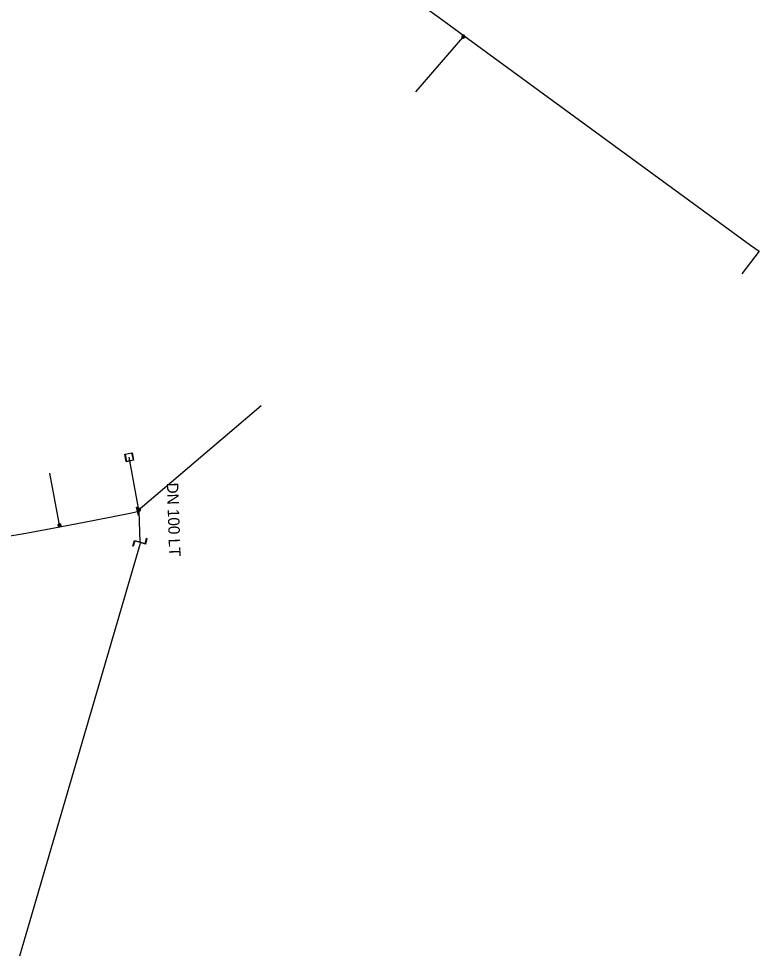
# Model space of a CAD drawing. Extents: x -832382 to -831581, y -1074670 to -1074251.
# Drawn here: x -831710.5 to -831580.8, y -1074667.1 to -1074502.9 of the extents above; entities that cross this region are included whole.
import ezdxf

# ---------------------------------------------------------------- set-up
doc = ezdxf.new("R2010")
doc.units = 0
for name, color, linetype in [('Přípojka vodovodu', 7, 'Continuous'), ('Přípojkový uzávěr', 7, 'Continuous'), ('Roz-řad', 7, 'Continuous'), ('Roz-řad-popis základní', 7, 'Continuous'), ('Změna materiálu vodovodu', 7, 'Continuous'), ('Řad-šoupě', 7, 'Continuous'), ('Šachta vodovodní', 7, 'Continuous')]:
    doc.layers.add(name, color=color, linetype=linetype)

msp = doc.modelspace()

# ---------------------------------------------------------------- linework, layer by layer
at = {"layer": 'Přípojka vodovodu'}
for points in [[(-831632.51, -1074505.89), (-831632.77, -1074506.19), (-831640.99, -1074515.72)], [(-831689.45, -1074588.91), (-831689.23, -1074588.69), (-831668.04, -1074570.68)], [(-831689.47, -1074589.15), (-831689.45, -1074588.91), (-831689.52, -1074588.66), (-831691.16, -1074579.71)], [(-831703.31, -1074591.9), (-831703.38, -1074591.62), (-831703.46, -1074591.27), (-831705.06, -1074582.5)]]:
    msp.add_lwpolyline(points, dxfattribs=at)
at = {"layer": 'Přípojkový uzávěr'}
for points in [[(-831632.64, -1074505.79), (-831632.57, -1074505.79), (-831632.51, -1074505.82), (-831632.45, -1074505.85), (-831632.42, -1074505.91), (-831632.39, -1074505.97), (-831632.39, -1074506.04), (-831632.39, -1074506.1), (-831632.42, -1074506.16), (-831632.45, -1074506.22), (-831632.51, -1074506.25), (-831632.57, -1074506.29), (-831632.64, -1074506.29), (-831632.7, -1074506.29), (-831632.76, -1074506.25), (-831632.82, -1074506.22), (-831632.85, -1074506.16), (-831632.89, -1074506.1), (-831632.89, -1074506.04), (-831632.89, -1074505.97), (-831632.85, -1074505.91), (-831632.82, -1074505.85), (-831632.76, -1074505.82), (-831632.7, -1074505.79), (-831632.64, -1074505.79)], [(-831632.64, -1074505.81), (-831632.69, -1074505.81), (-831632.75, -1074505.84), (-831632.8, -1074505.87), (-831632.83, -1074505.92), (-831632.86, -1074505.98), (-831632.86, -1074506.04), (-831632.86, -1074506.1), (-831632.83, -1074506.15), (-831632.8, -1074506.2), (-831632.75, -1074506.23), (-831632.7, -1074506.26), (-831632.64, -1074506.26), (-831632.58, -1074506.26), (-831632.52, -1074506.23), (-831632.47, -1074506.2), (-831632.44, -1074506.15), (-831632.41, -1074506.1), (-831632.41, -1074506.04), (-831632.41, -1074505.98), (-831632.44, -1074505.92), (-831632.47, -1074505.87), (-831632.53, -1074505.84), (-831632.58, -1074505.81), (-831632.64, -1074505.81)], [(-831632.64, -1074505.83), (-831632.58, -1074505.83), (-831632.53, -1074505.85), (-831632.48, -1074505.88), (-831632.46, -1074505.93), (-831632.43, -1074505.98), (-831632.43, -1074506.04), (-831632.43, -1074506.09), (-831632.46, -1074506.14), (-831632.48, -1074506.19), (-831632.53, -1074506.22), (-831632.58, -1074506.25), (-831632.64, -1074506.25), (-831632.69, -1074506.25), (-831632.74, -1074506.22), (-831632.79, -1074506.19), (-831632.82, -1074506.14), (-831632.85, -1074506.09), (-831632.85, -1074506.04), (-831632.85, -1074505.98), (-831632.82, -1074505.93), (-831632.79, -1074505.88), (-831632.74, -1074505.85), (-831632.69, -1074505.83), (-831632.64, -1074505.83)], [(-831632.64, -1074505.85), (-831632.72, -1074505.85), (-831632.77, -1074505.9), (-831632.82, -1074505.96), (-831632.82, -1074506.04), (-831632.82, -1074506.11), (-831632.77, -1074506.17), (-831632.71, -1074506.22), (-831632.64, -1074506.22), (-831632.56, -1074506.22), (-831632.5, -1074506.17), (-831632.45, -1074506.11), (-831632.45, -1074506.04), (-831632.45, -1074505.96), (-831632.5, -1074505.9), (-831632.56, -1074505.85), (-831632.64, -1074505.85)], [(-831632.64, -1074505.87), (-831632.57, -1074505.87), (-831632.52, -1074505.92), (-831632.47, -1074505.97), (-831632.47, -1074506.04), (-831632.47, -1074506.1), (-831632.52, -1074506.15), (-831632.57, -1074506.2), (-831632.64, -1074506.2), (-831632.71, -1074506.2), (-831632.75, -1074506.15), (-831632.8, -1074506.1), (-831632.8, -1074506.04), (-831632.8, -1074505.97), (-831632.75, -1074505.92), (-831632.71, -1074505.87), (-831632.64, -1074505.87)], [(-831632.64, -1074505.89), (-831632.7, -1074505.89), (-831632.74, -1074505.93), (-831632.78, -1074505.98), (-831632.78, -1074506.04), (-831632.78, -1074506.1), (-831632.74, -1074506.14), (-831632.7, -1074506.18), (-831632.64, -1074506.18), (-831632.58, -1074506.18), (-831632.54, -1074506.14), (-831632.49, -1074506.1), (-831632.49, -1074506.04), (-831632.49, -1074505.98), (-831632.54, -1074505.93), (-831632.58, -1074505.89), (-831632.64, -1074505.89)], [(-831632.64, -1074505.91), (-831632.58, -1074505.91), (-831632.55, -1074505.95), (-831632.51, -1074505.98), (-831632.51, -1074506.04), (-831632.51, -1074506.09), (-831632.55, -1074506.12), (-831632.59, -1074506.16), (-831632.64, -1074506.16), (-831632.69, -1074506.16), (-831632.73, -1074506.12), (-831632.76, -1074506.09), (-831632.76, -1074506.04), (-831632.76, -1074505.98), (-831632.73, -1074505.95), (-831632.69, -1074505.91), (-831632.64, -1074505.91)], [(-831632.64, -1074505.93), (-831632.68, -1074505.93), (-831632.71, -1074505.96), (-831632.74, -1074505.99), (-831632.74, -1074506.04), (-831632.74, -1074506.08), (-831632.71, -1074506.11), (-831632.68, -1074506.14), (-831632.64, -1074506.14), (-831632.6, -1074506.14), (-831632.57, -1074506.11), (-831632.54, -1074506.08), (-831632.54, -1074506.04), (-831632.54, -1074505.99), (-831632.57, -1074505.96), (-831632.6, -1074505.93), (-831632.64, -1074505.93)], [(-831632.64, -1074505.95), (-831632.6, -1074505.95), (-831632.58, -1074505.98), (-831632.55, -1074506), (-831632.55, -1074506.04), (-831632.55, -1074506.07), (-831632.58, -1074506.1), (-831632.6, -1074506.12), (-831632.64, -1074506.12), (-831632.67, -1074506.12), (-831632.7, -1074506.1), (-831632.72, -1074506.07), (-831632.72, -1074506.04), (-831632.72, -1074506), (-831632.7, -1074505.98), (-831632.67, -1074505.95), (-831632.64, -1074505.95)], [(-831632.64, -1074505.97), (-831632.66, -1074505.97), (-831632.68, -1074505.99), (-831632.7, -1074506.01), (-831632.7, -1074506.04), (-831632.7, -1074506.06), (-831632.68, -1074506.08), (-831632.66, -1074506.1), (-831632.64, -1074506.1), (-831632.61, -1074506.1), (-831632.59, -1074506.08), (-831632.57, -1074506.06), (-831632.57, -1074506.04), (-831632.57, -1074506.01), (-831632.59, -1074505.99), (-831632.61, -1074505.97), (-831632.64, -1074505.97)], [(-831632.64, -1074506), (-831632.62, -1074506), (-831632.61, -1074506.01), (-831632.6, -1074506.02), (-831632.6, -1074506.04), (-831632.6, -1074506.05), (-831632.61, -1074506.06), (-831632.62, -1074506.08), (-831632.64, -1074506.08), (-831632.65, -1074506.08), (-831632.66, -1074506.06), (-831632.68, -1074506.05), (-831632.68, -1074506.04), (-831632.68, -1074506.02), (-831632.66, -1074506.01), (-831632.65, -1074506), (-831632.64, -1074506)], [(-831632.64, -1074506.01), (-831632.65, -1074506.01), (-831632.65, -1074506.02), (-831632.66, -1074506.03), (-831632.66, -1074506.04), (-831632.66, -1074506.05), (-831632.65, -1074506.05), (-831632.65, -1074506.06), (-831632.64, -1074506.06), (-831632.63, -1074506.06), (-831632.62, -1074506.05), (-831632.61, -1074506.05), (-831632.61, -1074506.04), (-831632.61, -1074506.03), (-831632.62, -1074506.02), (-831632.63, -1074506.01), (-831632.64, -1074506.01)], [(-831689.45, -1074588.66), (-831689.39, -1074588.66), (-831689.33, -1074588.69), (-831689.27, -1074588.72), (-831689.23, -1074588.78), (-831689.2, -1074588.84), (-831689.2, -1074588.91), (-831689.2, -1074588.98), (-831689.23, -1074589.03), (-831689.27, -1074589.09), (-831689.33, -1074589.13), (-831689.39, -1074589.16), (-831689.45, -1074589.16), (-831689.51, -1074589.16), (-831689.57, -1074589.13), (-831689.63, -1074589.09), (-831689.67, -1074589.03), (-831689.7, -1074588.98), (-831689.7, -1074588.91), (-831689.7, -1074588.84), (-831689.67, -1074588.78), (-831689.63, -1074588.72), (-831689.57, -1074588.69), (-831689.51, -1074588.66), (-831689.45, -1074588.66)], [(-831689.45, -1074588.68), (-831689.51, -1074588.68), (-831689.56, -1074588.71), (-831689.62, -1074588.74), (-831689.65, -1074588.8), (-831689.68, -1074588.85), (-831689.68, -1074588.91), (-831689.68, -1074588.97), (-831689.65, -1074589.02), (-831689.62, -1074589.08), (-831689.56, -1074589.11), (-831689.51, -1074589.14), (-831689.45, -1074589.14), (-831689.39, -1074589.14), (-831689.34, -1074589.11), (-831689.28, -1074589.08), (-831689.25, -1074589.02), (-831689.22, -1074588.97), (-831689.22, -1074588.91), (-831689.22, -1074588.85), (-831689.25, -1074588.8), (-831689.28, -1074588.74), (-831689.34, -1074588.71), (-831689.39, -1074588.68), (-831689.45, -1074588.68)], [(-831689.45, -1074588.7), (-831689.4, -1074588.7), (-831689.35, -1074588.73), (-831689.3, -1074588.75), (-831689.27, -1074588.8), (-831689.24, -1074588.86), (-831689.24, -1074588.91), (-831689.24, -1074588.96), (-831689.27, -1074589.01), (-831689.3, -1074589.06), (-831689.35, -1074589.09), (-831689.4, -1074589.12), (-831689.45, -1074589.12), (-831689.5, -1074589.12), (-831689.55, -1074589.09), (-831689.6, -1074589.06), (-831689.63, -1074589.01), (-831689.66, -1074588.96), (-831689.66, -1074588.91), (-831689.66, -1074588.86), (-831689.63, -1074588.8), (-831689.6, -1074588.75), (-831689.55, -1074588.73), (-831689.5, -1074588.7), (-831689.45, -1074588.7)], [(-831689.45, -1074588.72), (-831689.53, -1074588.72), (-831689.58, -1074588.78), (-831689.64, -1074588.83), (-831689.64, -1074588.91), (-831689.64, -1074588.99), (-831689.58, -1074589.04), (-831689.53, -1074589.1), (-831689.45, -1074589.1), (-831689.37, -1074589.1), (-831689.32, -1074589.04), (-831689.26, -1074588.99), (-831689.26, -1074588.91), (-831689.26, -1074588.83), (-831689.32, -1074588.78), (-831689.37, -1074588.72), (-831689.45, -1074588.72)], [(-831689.45, -1074588.75), (-831689.38, -1074588.75), (-831689.33, -1074588.79), (-831689.29, -1074588.84), (-831689.29, -1074588.91), (-831689.29, -1074588.98), (-831689.33, -1074589.03), (-831689.38, -1074589.07), (-831689.45, -1074589.07), (-831689.52, -1074589.07), (-831689.57, -1074589.03), (-831689.61, -1074588.98), (-831689.61, -1074588.91), (-831689.61, -1074588.84), (-831689.57, -1074588.79), (-831689.52, -1074588.75), (-831689.45, -1074588.75)], [(-831689.45, -1074588.77), (-831689.51, -1074588.77), (-831689.55, -1074588.81), (-831689.59, -1074588.85), (-831689.59, -1074588.91), (-831689.59, -1074588.97), (-831689.55, -1074589.01), (-831689.51, -1074589.05), (-831689.45, -1074589.05), (-831689.39, -1074589.05), (-831689.35, -1074589.01), (-831689.31, -1074588.97), (-831689.31, -1074588.91), (-831689.31, -1074588.85), (-831689.35, -1074588.81), (-831689.39, -1074588.77), (-831689.45, -1074588.77)], [(-831689.45, -1074588.78), (-831689.4, -1074588.78), (-831689.36, -1074588.82), (-831689.33, -1074588.86), (-831689.33, -1074588.91), (-831689.33, -1074588.96), (-831689.36, -1074589), (-831689.4, -1074589.03), (-831689.45, -1074589.03), (-831689.5, -1074589.03), (-831689.54, -1074589), (-831689.58, -1074588.96), (-831689.58, -1074588.91), (-831689.58, -1074588.86), (-831689.54, -1074588.82), (-831689.5, -1074588.78), (-831689.45, -1074588.78)], [(-831689.45, -1074588.81), (-831689.49, -1074588.81), (-831689.52, -1074588.84), (-831689.55, -1074588.87), (-831689.55, -1074588.91), (-831689.55, -1074588.95), (-831689.52, -1074588.98), (-831689.49, -1074589.01), (-831689.45, -1074589.01), (-831689.41, -1074589.01), (-831689.38, -1074588.98), (-831689.35, -1074588.95), (-831689.35, -1074588.91), (-831689.35, -1074588.87), (-831689.38, -1074588.84), (-831689.41, -1074588.81), (-831689.45, -1074588.81)], [(-831689.45, -1074588.83), (-831689.42, -1074588.83), (-831689.39, -1074588.85), (-831689.37, -1074588.87), (-831689.37, -1074588.91), (-831689.37, -1074588.94), (-831689.39, -1074588.97), (-831689.42, -1074588.99), (-831689.45, -1074588.99), (-831689.49, -1074588.99), (-831689.51, -1074588.97), (-831689.53, -1074588.94), (-831689.53, -1074588.91), (-831689.53, -1074588.87), (-831689.51, -1074588.85), (-831689.49, -1074588.83), (-831689.45, -1074588.83)], [(-831689.45, -1074588.85), (-831689.48, -1074588.85), (-831689.49, -1074588.87), (-831689.51, -1074588.88), (-831689.51, -1074588.91), (-831689.51, -1074588.94), (-831689.49, -1074588.95), (-831689.48, -1074588.97), (-831689.45, -1074588.97), (-831689.42, -1074588.97), (-831689.41, -1074588.95), (-831689.39, -1074588.94), (-831689.39, -1074588.91), (-831689.39, -1074588.88), (-831689.41, -1074588.87), (-831689.42, -1074588.85), (-831689.45, -1074588.85)], [(-831689.45, -1074588.87), (-831689.43, -1074588.87), (-831689.42, -1074588.88), (-831689.41, -1074588.89), (-831689.41, -1074588.91), (-831689.41, -1074588.93), (-831689.42, -1074588.94), (-831689.43, -1074588.95), (-831689.45, -1074588.95), (-831689.47, -1074588.95), (-831689.48, -1074588.94), (-831689.49, -1074588.93), (-831689.49, -1074588.91), (-831689.49, -1074588.89), (-831689.48, -1074588.88), (-831689.47, -1074588.87), (-831689.45, -1074588.87)], [(-831689.45, -1074588.89), (-831689.46, -1074588.89), (-831689.47, -1074588.89), (-831689.47, -1074588.9), (-831689.47, -1074588.91), (-831689.47, -1074588.92), (-831689.47, -1074588.93), (-831689.46, -1074588.93), (-831689.45, -1074588.93), (-831689.44, -1074588.93), (-831689.43, -1074588.93), (-831689.43, -1074588.92), (-831689.43, -1074588.91), (-831689.43, -1074588.9), (-831689.43, -1074588.89), (-831689.44, -1074588.89), (-831689.45, -1074588.89)], [(-831703.38, -1074591.37), (-831703.32, -1074591.37), (-831703.26, -1074591.4), (-831703.2, -1074591.43), (-831703.16, -1074591.49), (-831703.13, -1074591.55), (-831703.13, -1074591.62), (-831703.13, -1074591.69), (-831703.16, -1074591.74), (-831703.2, -1074591.8), (-831703.26, -1074591.84), (-831703.32, -1074591.87), (-831703.38, -1074591.87), (-831703.44, -1074591.87), (-831703.5, -1074591.84), (-831703.56, -1074591.8), (-831703.6, -1074591.74), (-831703.63, -1074591.69), (-831703.63, -1074591.62), (-831703.63, -1074591.55), (-831703.6, -1074591.49), (-831703.56, -1074591.43), (-831703.5, -1074591.4), (-831703.44, -1074591.37), (-831703.38, -1074591.37)], [(-831703.38, -1074591.39), (-831703.44, -1074591.39), (-831703.49, -1074591.42), (-831703.55, -1074591.45), (-831703.58, -1074591.51), (-831703.61, -1074591.56), (-831703.61, -1074591.62), (-831703.61, -1074591.68), (-831703.58, -1074591.73), (-831703.55, -1074591.79), (-831703.49, -1074591.82), (-831703.44, -1074591.85), (-831703.38, -1074591.85), (-831703.32, -1074591.85), (-831703.27, -1074591.82), (-831703.21, -1074591.79), (-831703.18, -1074591.73), (-831703.15, -1074591.68), (-831703.15, -1074591.62), (-831703.15, -1074591.56), (-831703.18, -1074591.51), (-831703.21, -1074591.45), (-831703.27, -1074591.42), (-831703.32, -1074591.39), (-831703.38, -1074591.39)], [(-831703.38, -1074591.41), (-831703.33, -1074591.41), (-831703.28, -1074591.44), (-831703.23, -1074591.46), (-831703.2, -1074591.51), (-831703.17, -1074591.57), (-831703.17, -1074591.62), (-831703.17, -1074591.67), (-831703.2, -1074591.72), (-831703.23, -1074591.77), (-831703.28, -1074591.8), (-831703.33, -1074591.83), (-831703.38, -1074591.83), (-831703.43, -1074591.83), (-831703.48, -1074591.8), (-831703.53, -1074591.77), (-831703.56, -1074591.72), (-831703.59, -1074591.67), (-831703.59, -1074591.62), (-831703.59, -1074591.57), (-831703.56, -1074591.51), (-831703.53, -1074591.46), (-831703.48, -1074591.44), (-831703.43, -1074591.41), (-831703.38, -1074591.41)], [(-831703.38, -1074591.43), (-831703.46, -1074591.43), (-831703.51, -1074591.49), (-831703.57, -1074591.54), (-831703.57, -1074591.62), (-831703.57, -1074591.7), (-831703.51, -1074591.75), (-831703.46, -1074591.81), (-831703.38, -1074591.81), (-831703.3, -1074591.81), (-831703.25, -1074591.75), (-831703.19, -1074591.7), (-831703.19, -1074591.62), (-831703.19, -1074591.54), (-831703.25, -1074591.49), (-831703.3, -1074591.43), (-831703.38, -1074591.43)], [(-831703.38, -1074591.46), (-831703.31, -1074591.46), (-831703.26, -1074591.5), (-831703.22, -1074591.55), (-831703.22, -1074591.62), (-831703.22, -1074591.69), (-831703.26, -1074591.74), (-831703.31, -1074591.78), (-831703.38, -1074591.78), (-831703.45, -1074591.78), (-831703.5, -1074591.74), (-831703.54, -1074591.69), (-831703.54, -1074591.62), (-831703.54, -1074591.55), (-831703.5, -1074591.5), (-831703.45, -1074591.46), (-831703.38, -1074591.46)], [(-831703.38, -1074591.48), (-831703.44, -1074591.48), (-831703.48, -1074591.52), (-831703.52, -1074591.56), (-831703.52, -1074591.62), (-831703.52, -1074591.68), (-831703.48, -1074591.72), (-831703.44, -1074591.76), (-831703.38, -1074591.76), (-831703.32, -1074591.76), (-831703.28, -1074591.72), (-831703.24, -1074591.68), (-831703.24, -1074591.62), (-831703.24, -1074591.56), (-831703.28, -1074591.52), (-831703.32, -1074591.48), (-831703.38, -1074591.48)], [(-831703.38, -1074591.5), (-831703.33, -1074591.5), (-831703.29, -1074591.53), (-831703.26, -1074591.57), (-831703.26, -1074591.62), (-831703.26, -1074591.67), (-831703.29, -1074591.71), (-831703.33, -1074591.75), (-831703.38, -1074591.75), (-831703.43, -1074591.75), (-831703.47, -1074591.71), (-831703.51, -1074591.67), (-831703.51, -1074591.62), (-831703.51, -1074591.57), (-831703.47, -1074591.53), (-831703.43, -1074591.5), (-831703.38, -1074591.5)], [(-831703.38, -1074591.52), (-831703.42, -1074591.52), (-831703.45, -1074591.55), (-831703.48, -1074591.58), (-831703.48, -1074591.62), (-831703.48, -1074591.66), (-831703.45, -1074591.69), (-831703.42, -1074591.72), (-831703.38, -1074591.72), (-831703.34, -1074591.72), (-831703.31, -1074591.69), (-831703.28, -1074591.66), (-831703.28, -1074591.62), (-831703.28, -1074591.58), (-831703.31, -1074591.55), (-831703.34, -1074591.52), (-831703.38, -1074591.52)], [(-831703.38, -1074591.54), (-831703.35, -1074591.54), (-831703.32, -1074591.56), (-831703.3, -1074591.58), (-831703.3, -1074591.62), (-831703.3, -1074591.65), (-831703.32, -1074591.68), (-831703.35, -1074591.7), (-831703.38, -1074591.7), (-831703.42, -1074591.7), (-831703.44, -1074591.68), (-831703.46, -1074591.65), (-831703.46, -1074591.62), (-831703.46, -1074591.58), (-831703.44, -1074591.56), (-831703.42, -1074591.54), (-831703.38, -1074591.54)], [(-831703.38, -1074591.56), (-831703.41, -1074591.56), (-831703.42, -1074591.58), (-831703.44, -1074591.59), (-831703.44, -1074591.62), (-831703.44, -1074591.65), (-831703.42, -1074591.66), (-831703.41, -1074591.68), (-831703.38, -1074591.68), (-831703.35, -1074591.68), (-831703.34, -1074591.66), (-831703.32, -1074591.65), (-831703.32, -1074591.62), (-831703.32, -1074591.59), (-831703.34, -1074591.58), (-831703.35, -1074591.56), (-831703.38, -1074591.56)], [(-831703.38, -1074591.58), (-831703.36, -1074591.58), (-831703.35, -1074591.59), (-831703.34, -1074591.6), (-831703.34, -1074591.62), (-831703.34, -1074591.64), (-831703.35, -1074591.65), (-831703.36, -1074591.66), (-831703.38, -1074591.66), (-831703.4, -1074591.66), (-831703.41, -1074591.65), (-831703.42, -1074591.64), (-831703.42, -1074591.62), (-831703.42, -1074591.6), (-831703.41, -1074591.59), (-831703.4, -1074591.58), (-831703.38, -1074591.58)], [(-831703.38, -1074591.6), (-831703.39, -1074591.6), (-831703.4, -1074591.6), (-831703.4, -1074591.61), (-831703.4, -1074591.62), (-831703.4, -1074591.63), (-831703.4, -1074591.64), (-831703.39, -1074591.64), (-831703.38, -1074591.64), (-831703.37, -1074591.64), (-831703.36, -1074591.64), (-831703.36, -1074591.63), (-831703.36, -1074591.62), (-831703.36, -1074591.61), (-831703.36, -1074591.6), (-831703.37, -1074591.6), (-831703.38, -1074591.6)]]:
    msp.add_open_spline(points, degree=3, dxfattribs=at)
at = {"layer": 'Roz-řad'}
msp.add_line((-831689.26, -1074594.84), (-831710.36, -1074667.11), dxfattribs=at)
for points in [[(-831670.1, -1074478.78), (-831661.15, -1074485.22), (-831659.02, -1074486.76), (-831652.41, -1074491.52), (-831636.89, -1074502.69), (-831632.51, -1074505.89), (-831582.31, -1074542.55), (-831580.8, -1074543.6), (-831583.87, -1074547.6)], [(-831717.16, -1074594.32), (-831709.92, -1074593.1), (-831703.31, -1074591.9), (-831697.22, -1074590.71), (-831690.97, -1074589.49), (-831689.47, -1074589.15), (-831689.29, -1074594.6)]]:
    msp.add_lwpolyline(points, dxfattribs=at)
at = {"layer": 'Změna materiálu vodovodu'}
msp.add_lwpolyline([(-831690.2, -1074594.37), (-831690.47, -1074595.3), (-831690.53, -1074595.28), (-831690.24, -1074594.29), (-831688.38, -1074594.83), (-831688.11, -1074593.9), (-831688.05, -1074593.92), (-831688.34, -1074594.91), (-831690.2, -1074594.37)], dxfattribs=at)
at = {"layer": 'Řad-šoupě'}
msp.add_lwpolyline([(-831689.55, -1074589.94), (-831689.87, -1074588.47), (-831689.83, -1074588.46), (-831689.51, -1074589.93), (-831689.55, -1074589.94)], dxfattribs=at)
at = {"layer": 'Šachta vodovodní'}
for points in [[(-831690.39, -1074580.21), (-831691.67, -1074580.47), (-831691.93, -1074579.2), (-831690.65, -1074578.94), (-831690.39, -1074580.21)], [(-831690.68, -1074578.99), (-831691.88, -1074579.23), (-831691.63, -1074580.43), (-831690.44, -1074580.18), (-831690.68, -1074578.99)]]:
    msp.add_lwpolyline(points, dxfattribs=at)

# ---------------------------------------------------------------- texts
at = {"layer": 'Roz-řad-popis základní'}
msp.add_text('DN 100 LT', height=2, rotation=271.8916, dxfattribs=at).set_placement((-831684.58, -1074584.19))

doc.saveas('drawing.dxf')
